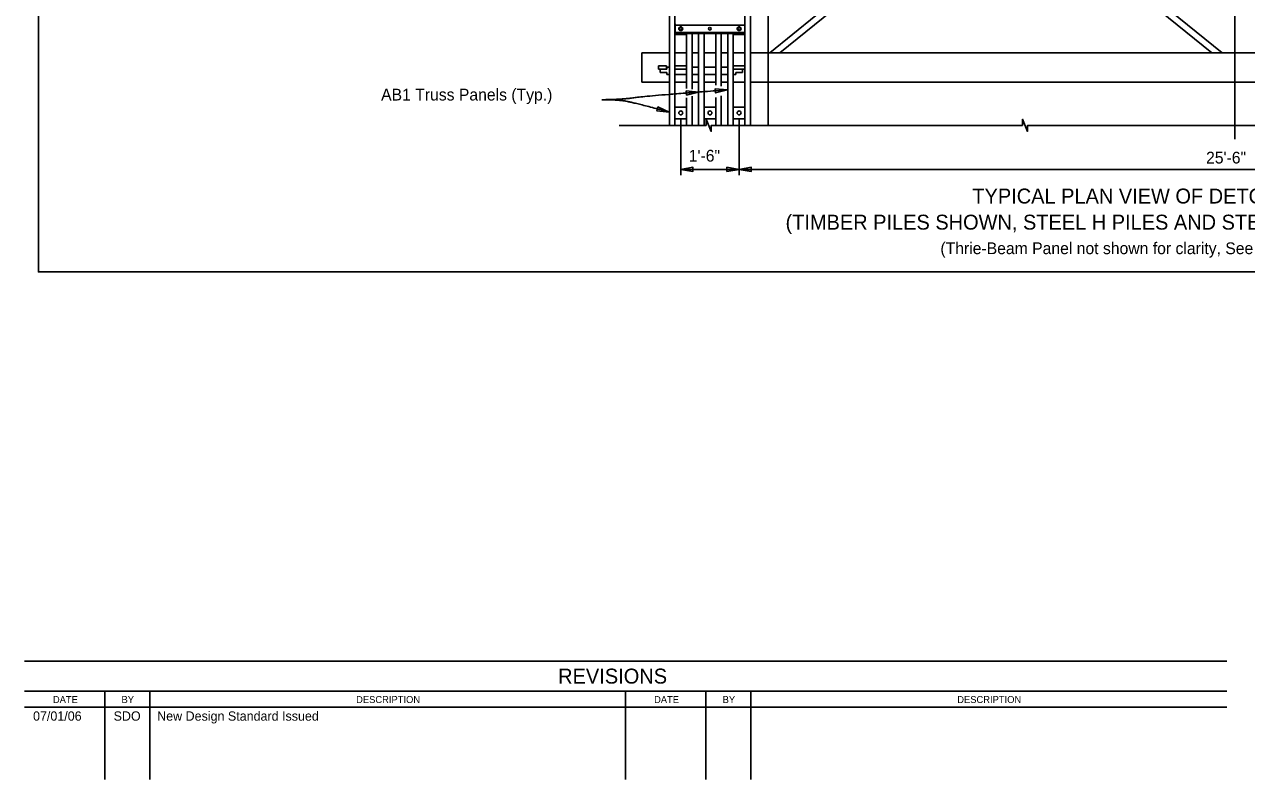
# Model space of a CAD drawing. Extents: x 10618 to 10724, y 76431 to 76484.
# Drawn here: x 10617.64 to 10649.06, y 76431.37 to 76450.8 of the extents above; entities that cross this region are included whole.
import ezdxf

# ---------------------------------------------------------------- set-up
doc = ezdxf.new("R2010")
doc.units = 0
for name, color, linetype in [('ActivePts-ConstElements', 7, 'Continuous'), ('Border', 7, 'Continuous'), ('CL_Minor', 7, 'Continuous'), ('Dimension', 7, 'Continuous'), ('SteelMisc', 7, 'Continuous'), ('SteelMisc_h', 7, 'Continuous'), ('Symbols', 7, 'Continuous'), ('TextStructures', 7, 'Continuous')]:
    doc.layers.add(name, color=color, linetype=linetype)

msp = doc.modelspace()

# ---------------------------------------------------------------- linework, layer by layer
at = {"layer": 'ActivePts-ConstElements'}
msp.add_lwpolyline([(10617.994, 76484.026), (10679.594, 76484.026), (10679.594, 76444.426), (10617.994, 76444.426)], close=True, dxfattribs=at)
at = {"layer": 'Border'}
for p, q in [((10648.553, 76434.413), (10617.636, 76434.413)), ((10648.553, 76433.64), (10617.636, 76433.64)), ((10619.701, 76433.64), (10619.701, 76431.368)), ((10620.861, 76433.64), (10620.861, 76431.368)), ((10633.095, 76433.64), (10633.095, 76431.368)), ((10635.16, 76433.64), (10635.16, 76431.368)), ((10636.32, 76433.64), (10636.32, 76431.368)), ((10617.636, 76433.23), (10648.553, 76433.23))]:
    msp.add_line(p, q, dxfattribs=at)
at = {"layer": 'CL_Minor'}
msp.add_lwpolyline([(10648.764, 76447.841), (10648.764, 76451.455)], dxfattribs=at)
at = {"layer": 'Dimension'}
for p, q in [((10634.514, 76448.368), (10634.514, 76446.915)), ((10636.014, 76448.368), (10636.014, 76446.915)), ((10634.514, 76447.066), (10663.013, 76447.066))]:
    msp.add_line(p, q, dxfattribs=at)
for points in [[(10634.972, 76449.053), (10634.657, 76449.084), (10634.664, 76448.978)], [(10635.716, 76449.11), (10635.401, 76449.14), (10635.409, 76449.035)], [(10634.215, 76448.542), (10633.927, 76448.674), (10633.9, 76448.571)], [(10634.514, 76447.066), (10634.826, 76447.013), (10634.826, 76447.119)], [(10636.014, 76447.066), (10635.701, 76447.013), (10635.701, 76447.119)], [(10636.014, 76447.066), (10636.326, 76447.013), (10636.326, 76447.119)]]:
    msp.add_lwpolyline(points, close=True, dxfattribs=at)
for points in [[(10632.485, 76448.859), (10632.974, 76448.859), (10633.713, 76448.965), (10635.716, 76449.11)], [(10632.485, 76448.859), (10632.894, 76448.859), (10633.308, 76448.784), (10634.215, 76448.542)]]:
    msp.add_open_spline(points, degree=2, dxfattribs=at)
at = {"layer": 'SteelMisc'}
for p, q in [((10636.764, 76474.685), (10636.764, 76448.199)), ((10636.162, 76462.269), (10636.162, 76448.199)), ((10636.305, 76452.002), (10636.305, 76448.199)), ((10634.365, 76451.354), (10634.365, 76448.199)), ((10634.222, 76451.246), (10634.222, 76448.199)), ((10634.368, 76450.56), (10634.368, 76450.81)), ((10636.159, 76450.78), (10634.368, 76450.78)), ((10636.159, 76450.56), (10636.159, 76450.81)), ((10634.662, 76450.537), (10634.365, 76450.537)), ((10636.159, 76450.591), (10634.368, 76450.591)), ((10636.159, 76450.56), (10634.368, 76450.56)), ((10634.662, 76450.56), (10634.662, 76449.149)), ((10634.805, 76450.56), (10634.805, 76449.129)), ((10634.972, 76450.56), (10634.972, 76448.199)), ((10635.115, 76450.56), (10635.115, 76448.199)), ((10635.412, 76450.56), (10635.412, 76449.229)), ((10635.555, 76450.56), (10635.555, 76449.204)), ((10635.722, 76450.56), (10635.722, 76448.199)), ((10635.865, 76450.56), (10635.865, 76448.199)), ((10636.162, 76450.537), (10635.865, 76450.537)), ((10633.514, 76450.061), (10633.514, 76449.311)), ((10634.222, 76450.061), (10633.514, 76450.061)), ((10634.662, 76450.061), (10634.365, 76450.061)), ((10634.972, 76450.061), (10634.805, 76450.061)), ((10635.412, 76450.061), (10635.115, 76450.061)), ((10635.722, 76450.061), (10635.555, 76450.061)), ((10636.162, 76450.061), (10635.865, 76450.061)), ((10633.938, 76449.726), (10634.147, 76449.726)), ((10633.938, 76449.726), (10633.938, 76449.645)), ((10634.147, 76449.726), (10634.147, 76449.645)), ((10634.16, 76449.697), (10634.222, 76449.697)), ((10634.16, 76449.697), (10634.16, 76449.645)), ((10634.365, 76449.726), (10634.662, 76449.726)), ((10634.365, 76449.726), (10634.662, 76449.726)), ((10634.972, 76449.697), (10634.805, 76449.697)), ((10635.412, 76449.697), (10635.115, 76449.697)), ((10635.722, 76449.697), (10635.555, 76449.697)), ((10635.865, 76449.726), (10636.162, 76449.726)), ((10634.16, 76449.645), (10633.938, 76449.645)), ((10633.984, 76449.562), (10633.984, 76449.645)), ((10633.984, 76449.562), (10634.16, 76449.562)), ((10634.16, 76449.51), (10634.16, 76449.562)), ((10634.16, 76449.51), (10634.222, 76449.51)), ((10634.662, 76449.645), (10634.365, 76449.645)), ((10634.662, 76449.645), (10634.365, 76449.645)), ((10634.662, 76449.51), (10634.365, 76449.51)), ((10634.972, 76449.51), (10634.805, 76449.51)), ((10635.412, 76449.51), (10635.115, 76449.51)), ((10635.722, 76449.51), (10635.555, 76449.51)), ((10636.162, 76449.645), (10635.865, 76449.645)), ((10635.927, 76449.51), (10635.865, 76449.51)), ((10636.103, 76449.562), (10635.927, 76449.562)), ((10635.927, 76449.51), (10635.927, 76449.562)), ((10636.103, 76449.562), (10636.103, 76449.645)), ((10634.222, 76449.311), (10633.514, 76449.311)), ((10634.662, 76449.311), (10634.365, 76449.311)), ((10634.972, 76449.311), (10634.805, 76449.311)), ((10635.412, 76449.311), (10635.115, 76449.311)), ((10635.722, 76449.311), (10635.555, 76449.311)), ((10636.162, 76449.311), (10635.865, 76449.311)), ((10634.662, 76448.91), (10634.662, 76448.199)), ((10634.805, 76448.948), (10634.805, 76448.199)), ((10635.412, 76448.912), (10635.412, 76448.199)), ((10635.555, 76448.955), (10635.555, 76448.199)), ((10634.662, 76448.667), (10634.365, 76448.667)), ((10635.412, 76448.667), (10635.115, 76448.667)), ((10636.162, 76448.667), (10635.865, 76448.667)), ((10634.662, 76448.37), (10634.365, 76448.37)), ((10635.412, 76448.37), (10635.115, 76448.37)), ((10636.162, 76448.37), (10635.865, 76448.37))]:
    msp.add_line(p, q, dxfattribs=at)
for centre, radius in [((10634.514, 76450.685), 0.0495), ((10634.514, 76450.685), 0.0339), ((10635.264, 76450.685), 0.0339), ((10636.014, 76450.685), 0.0495), ((10636.014, 76450.685), 0.0339), ((10634.514, 76448.519), 0.0495), ((10635.264, 76448.519), 0.0495), ((10636.014, 76448.519), 0.0495)]:
    msp.add_circle(centre, radius, dxfattribs=at)
at = {"layer": 'SteelMisc_h'}
for p, q in [((10636.801, 76450.061), (10642.025, 76454.311)), ((10637.065, 76450.061), (10642.289, 76454.311)), ((10646.342, 76451.548), (10648.171, 76450.061)), ((10646.617, 76451.539), (10648.435, 76450.061)), ((10636.305, 76450.061), (10661.222, 76450.061)), ((10636.305, 76449.311), (10661.222, 76449.311))]:
    msp.add_line(p, q, dxfattribs=at)
at = {"layer": 'Symbols'}
for points in [[(10639.799, 76448.199), (10635.298, 76448.199), (10635.298, 76448.044), (10635.163, 76448.354), (10635.163, 76448.199), (10632.934, 76448.199)], [(10648.764, 76448.199), (10643.435, 76448.199), (10643.435, 76448.044), (10643.3, 76448.354), (10643.3, 76448.199), (10639.799, 76448.199)], [(10658.443, 76448.199), (10654.718, 76448.199), (10654.718, 76448.044), (10654.583, 76448.354), (10654.583, 76448.199), (10648.764, 76448.199)]]:
    msp.add_lwpolyline(points, dxfattribs=at)

# ---------------------------------------------------------------- texts
at = {"layer": 'Dimension'}
for s, p in [('1\'-6"', (10634.719, 76447.266)), ('25\'-6"', (10648.023, 76447.217)), ('(Thrie-Beam Panel not shown for clarity, See Index 102-240)', (10641.191, 76444.885))]:
    msp.add_text(s, height=0.3024, dxfattribs=at).set_placement(p)
at = {"layer": 'TextStructures'}
for s, height, p in [('AB1 Truss Panels (Typ.)', 0.3024, (10626.808, 76448.838)), ('TYPICAL PLAN VIEW OF DETOUR BRIDGE', 0.384, (10642.013, 76446.188)), ('(TIMBER PILES SHOWN, STEEL H PILES AND STEEL PIPE PILES SIMILAR)', 0.384, (10637.209, 76445.516)), ('REVISIONS', 0.385, (10631.359, 76433.837)), ('BY', 0.1802, (10620.132, 76433.336)), ('BY', 0.1802, (10635.591, 76433.336)), ('07/01/06', 0.24, (10617.857, 76432.882)), ('SDO', 0.24, (10619.929, 76432.882)), ('New Design Standard Issued', 0.24, (10621.049, 76432.882))]:
    msp.add_text(s, height=height, dxfattribs=at).set_placement(p)
for s, height, rotation, p in [('DATE', 0.1794, 359.8693, (10618.368, 76433.337)), ('DESCRIPTION', 0.1801, 0.0498, (10626.165, 76433.336)), ('DATE', 0.1794, 359.8693, (10633.828, 76433.337)), ('DESCRIPTION', 0.1801, 0.0498, (10641.624, 76433.336))]:
    msp.add_text(s, height=height, rotation=rotation, dxfattribs=at).set_placement(p)

doc.saveas('drawing.dxf')
